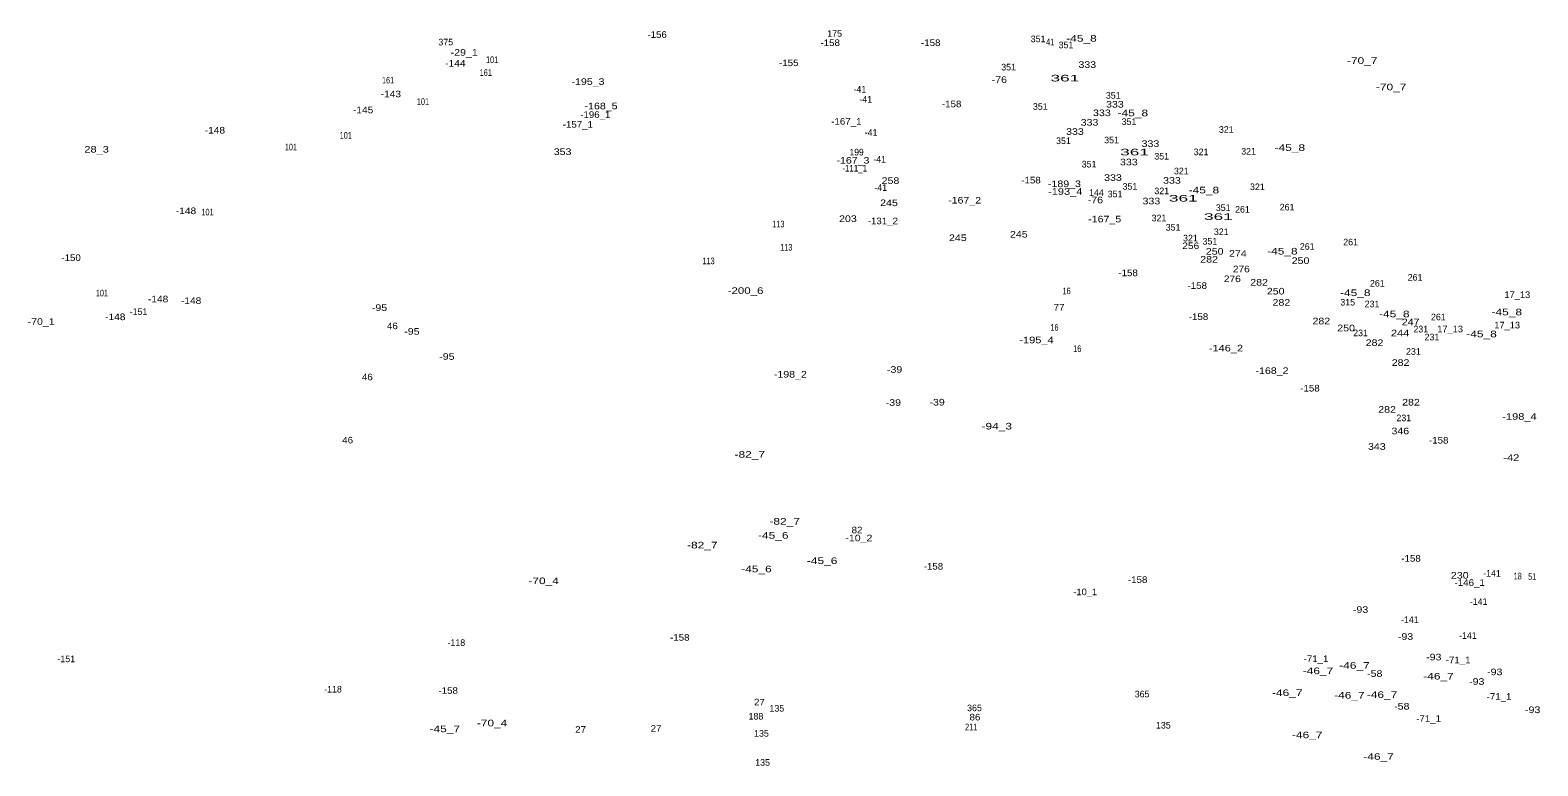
# Model space of a CAD drawing. Extents: x -662996 to -659766, y -998554 to -993949.
# Drawn here: x -661500 to -660587, y -997860 to -997415 of the extents above; entities that cross this region are included whole.
import ezdxf
from ezdxf.enums import TextEntityAlignment as Align

# ---------------------------------------------------------------- set-up
doc = ezdxf.new("R2010")
doc.units = 0
doc.header["$LTSCALE"] = 1.6
doc.layers.add('24', color=7, linetype='Continuous')

msp = doc.modelspace()

# ---------------------------------------------------------------- texts
at = {"layer": '24'}
for s, width, p in [('-156', 1.1, (-661120.29, -997419.77)), ('-29_1', 1.2, (-661237.091, -997430.59)), ('-158', 1.1, (-661015.5, -997424.74)), ('-158', 1.1, (-660954.64, -997424.74)), ('41', 0.85, (-660882.27, -997424.26)), ('-45_8', 1.35, (-660863.36, -997422.11)), ('-144', 1.15, (-661242.45, -997437.19)), ('101', 0.8, (-661220.2, -997434.99)), ('-155', 1.1, (-661040.581, -997436.9)), ('333', 1.2, (-660859.84, -997437.96)), ('-70_7', 1.35, (-660693.39, -997435.52)), ('161', 0.8, (-661283.181, -997447.39)), ('161', 0.8, (-661224.041, -997442.78)), ('-195_3', 1.2, (-661162.15, -997448.25)), ('-76', 1.2, (-660913.11, -997447.1)), ('361', 1.95, (-660873.423, -997446.17)), ('-143', 1.15, (-661281.52, -997455.72)), ('-70_7', 1.35, (-660675.87, -997451.52)), ('-145', 1.15, (-661298.31, -997465.43)), ('101', 0.8, (-661262.06, -997460.35)), ('-168_5', 1.2, (-661154.24, -997463.01)), ('-158', 1.1, (-660941.971, -997461.81)), ('333', 1.2, (-660851, -997467.15)), ('333', 1.2, (-660843.13, -997461.97)), ('-45_8', 1.35, (-660832.25, -997467.25)), ('-157_1', 1.1, (-661168.301, -997474.16)), ('-196_1', 1.1, (-661157.71, -997468.22)), ('-167_1', 1.1, (-661005.71, -997472.34)), ('333', 1.2, (-660858.49, -997472.92)), ('-148', 1.15, (-661388.05, -997477.68)), ('101', 0.8, (-661308.81, -997480.77)), ('333', 1.2, (-660867.319, -997478.48)), ('333', 1.2, (-660821.62, -997485.79)), ('28_3', 1.25, (-661459.66, -997489.21)), ('101', 0.8, (-661342.03, -997487.88)), ('353', 1.2, (-661177.53, -997490.67)), ('199', 0.95, (-660999.49, -997490.95)), ('361', 1.95, (-660831.233, -997490.92)), ('-45_8', 1.35, (-660737.21, -997488.19)), ('-167_3', 1.2, (-661001.73, -997495.92)), ('-111_1', 0.9, (-661000.67, -997500.68)), ('333', 1.2, (-660834.679, -997496.93)), ('258', 1.2, (-660979.01, -997508.19)), ('-158', 1.1, (-660893.921, -997507.89)), ('-189_3', 1.2, (-660873.671, -997510.12)), ('333', 1.2, (-660844.29, -997506.34)), ('333', 1.2, (-660808.579, -997508.06)), ('245', 1.2, (-660979.91, -997521.62)), ('-167_2', 1.2, (-660934.11, -997520.06)), ('-193_4', 1.25, (-660873.19, -997514.75)), ('-76', 1.2, (-660854.939, -997519.9)), ('333', 1.2, (-660821.049, -997520.55)), ('361', 1.95, (-660801.723, -997518.85)), ('-45_8', 1.35, (-660789.24, -997513.93)), ('-148', 1.15, (-661405.53, -997526.47)), ('101', 0.8, (-661392.53, -997527.25)), ('203', 1.2, (-661004.77, -997531.22)), ('-167_5', 1.2, (-660849.3, -997531.47)), ('361', 1.95, (-660780.473, -997529.96)), ('113', 0.8, (-661046.9, -997534.49)), ('-131_2', 1.1, (-660983.61, -997532.57)), ('245', 1.2, (-660901.29, -997540.67)), ('113', 0.8, (-661042.1, -997548.51)), ('245', 1.2, (-660938.209, -997542.77)), ('256', 1.15, (-660797.19, -997547.62)), ('-150', 1.1, (-661475.12, -997554.83)), ('113', 0.8, (-661089.14, -997556.77)), ('282', 1.2, (-660786.1, -997555.81)), ('250', 1.2, (-660782.709, -997551.01)), ('274', 1.2, (-660768.67, -997552.29)), ('-45_8', 1.35, (-660741.74, -997550.9)), ('250', 1.2, (-660730.73, -997556.63)), ('-158', 1.1, (-660835.13, -997564.01)), ('276', 1.15, (-660772.03, -997567.62)), ('276', 1.15, (-660766.6, -997561.71)), ('101', 0.8, (-661456.46, -997576.23)), ('-200_6', 1.3, (-661066.75, -997574.76)), ('16', 0.8, (-660872.341, -997574.94)), ('-158', 1.1, (-660793.27, -997571.69)), ('282', 1.2, (-660755.829, -997569.71)), ('250', 1.2, (-660745.77, -997575.1)), ('-45_8', 1.35, (-660697.58, -997576.06)), ('17_13', 1.05, (-660599.48, -997577.2)), ('-148', 1.15, (-661422.42, -997579.86)), ('-148', 1.15, (-661402.45, -997580.82)), ('-95', 1.2, (-661288.39, -997585.07)), ('77', 1.1, (-660876.931, -997584.83)), ('282', 1.2, (-660742.309, -997581.9)), ('-70_1', 1.2, (-661493.231, -997593.46)), ('-148', 1.15, (-661448.34, -997590.62)), ('-158', 1.1, (-660792.51, -997590.52)), ('282', 1.2, (-660718.13, -997593.14)), ('-45_8', 1.35, (-660673.96, -997588.9)), ('247', 1.2, (-660664.06, -997593.71)), ('-45_8', 1.35, (-660605.84, -997587.71)), ('46', 1.1, (-661280.59, -997596.1)), ('-95', 1.2, (-661268.77, -997599.45)), ('-195_4', 1.25, (-660890.58, -997604.61)), ('16', 0.8, (-660879.731, -997597.03)), ('250', 1.2, (-660703.14, -997597.39)), ('244', 1.25, (-660670.44, -997600.43)), ('17_13', 1.05, (-660640.18, -997597.94)), ('-45_8', 1.35, (-660621.15, -997601)), ('17_13', 1.05, (-660605.62, -997595.64)), ('16', 0.8, (-660865.9, -997609.9)), ('-146_2', 1.25, (-660775.89, -997609.57)), ('282', 1.2, (-660685.949, -997606.29)), ('-95', 1.2, (-661247.58, -997614.62)), ('-39', 1.2, (-660976.5, -997622.49)), ('282', 1.2, (-660670.15, -997618.29)), ('46', 1.1, (-661295.76, -997627.03)), ('-198_2', 1.2, (-661039.64, -997625.38)), ('-168_2', 1.2, (-660748.01, -997623.22)), ('-158', 1.1, (-660725.03, -997633.81)), ('-39', 1.2, (-660977.26, -997642.47)), ('-39', 1.2, (-660950.77, -997642.28)), ('282', 1.2, (-660678.329, -997646.67)), ('282', 1.2, (-660663.86, -997642.29)), ('-94_3', 1.35, (-660914.67, -997656.79)), ('-198_4', 1.25, (-660598.17, -997650.94)), ('46', 1.1, (-661307.66, -997665.25)), ('346', 1.2, (-660670.33, -997659.69)), ('-158', 1.1, (-660647.081, -997665.31)), ('-82_7', 1.35, (-661064.19, -997673.86)), ('343', 1.2, (-660684.54, -997669.09)), ('-42', 1.25, (-660603.11, -997675.84)), ('-45_6', 1.35, (-661049.96, -997722.88)), ('-82_7', 1.35, (-661043.06, -997714.39)), ('82', 1.1, (-660999.27, -997719.64)), ('-82_7', 1.35, (-661092.95, -997728.78)), ('-10_2', 1.2, (-660998.14, -997724.44)), ('-45_6', 1.35, (-661020.39, -997738.24)), ('-158', 1.1, (-660663.821, -997736.81)), ('-70_4', 1.35, (-661189.01, -997750.38)), ('-45_6', 1.35, (-661060.14, -997743.24)), ('-158', 1.1, (-660952.981, -997741.62)), ('-158', 1.1, (-660829.351, -997749.67)), ('230', 1.2, (-660634.319, -997747.05)), ('18', 0.8, (-660599.23, -997747.52)), ('51', 0.8, (-660590.5, -997747.77)), ('-10_1', 1.05, (-660861.1, -997757.09)), ('-146_1', 1.1, (-660628.31, -997751.44)), ('-93', 1.2, (-660694.37, -997767.78)), ('-158', 1.1, (-661106.571, -997784.63)), ('-93', 1.2, (-660667.16, -997784.11)), ('-46_7', 1.35, (-660720.16, -997804.86)), ('-71_1', 1.1, (-660721.361, -997797.51)), ('-46_7', 1.35, (-660698.081, -997801.59)), ('-93', 1.2, (-660650.06, -997796.55)), ('-71_1', 1.1, (-660635.301, -997798.27)), ('-93', 1.2, (-660613.14, -997805.5)), ('-58', 1.2, (-660685.8, -997806.5)), ('-46_7', 1.35, (-660647.201, -997808.12)), ('-93', 1.2, (-660624.02, -997811.33)), ('-158', 1.1, (-661246.801, -997816.77)), ('-46_7', 1.35, (-660738.78, -997818.11)), ('-46_7', 1.35, (-660701.15, -997819.65)), ('-46_7', 1.35, (-660681.37, -997819.26)), ('-71_1', 1.1, (-660610.551, -997820.37)), ('27', 1.1, (-661058.34, -997823.81)), ('86', 1.1, (-660927.87, -997832.88)), ('-58', 1.2, (-660669.42, -997826.31)), ('-93', 1.2, (-660590.2, -997828.44)), ('-45_7', 1.35, (-661248.85, -997840)), ('-70_4', 1.35, (-661220.23, -997836.46)), ('27', 1.1, (-661166.63, -997840.33)), ('27', 1.1, (-661120.94, -997839.75)), ('211', 0.8, (-660930.14, -997838.81)), ('-71_1', 1.1, (-660653.201, -997833.7)), ('-46_7', 1.35, (-660726.691, -997843.66)), ('-46_7', 1.35, (-660683.49, -997856.72))]:
    msp.add_text(s, height=4, dxfattribs=dict(at, width=width)).set_placement(p, align=Align.CENTER)
for s, p in [('175', (-661012.811, -997419.13)), ('375', (-661248.273, -997424.36)), ('351', (-660889.65, -997422.41)), ('351', (-660872.75, -997426.06)), ('351', (-660907.5, -997439.5)), ('-41', (-660997.55, -997452.92)), ('351', (-660844.14, -997456.6)), ('-41', (-660993.99, -997458.97)), ('351', (-660888.299, -997463.32)), ('351', (-660834.579, -997472.49)), ('-41', (-660990.73, -997479.02)), ('351', (-660874.29, -997484.07)), ('351', (-660845.14, -997483.63)), ('321', (-660775.699, -997477.26)), ('351', (-660814.799, -997493.43)), ('321', (-660790.929, -997490.79)), ('321', (-660762.179, -997490.41)), ('-41', (-660985.54, -997495.26)), ('351', (-660858.77, -997498.23)), ('321', (-660802.929, -997502.41)), ('-41', (-660984.91, -997512.39)), ('351', (-660834, -997511.67)), ('321', (-660756.85, -997511.93)), ('144', (-660854.31, -997515.44)), ('351', (-660843.03, -997516.28)), ('321', (-660814.76, -997514.39)), ('321', (-660816.449, -997530.79)), ('351', (-660777.549, -997524.54)), ('261', (-660765.91, -997525.57)), ('261', (-660738.87, -997524.24)), ('351', (-660807.89, -997536.45)), ('321', (-660778.74, -997539.15)), ('321', (-660797.41, -997542.98)), ('351', (-660785.62, -997544.9)), ('261', (-660726.701, -997548.04)), ('261', (-660700.41, -997545.37)), ('261', (-660661.38, -997566.71)), ('261', (-660684.24, -997570.33)), ('315', (-660702.179, -997581.76)), ('231', (-660687.439, -997582.82)), ('-151', (-661434.27, -997587.5)), ('261', (-660647.291, -997590.71)), ('231', (-660694.39, -997600.34)), ('231', (-660657.929, -997598.06)), ('231', (-660651.16, -997602.86)), ('231', (-660662.4, -997611.58)), ('231', (-660668.209, -997651.77)), ('-141', (-660614.81, -997745.86)), ('-141', (-660622.87, -997762.95)), ('-141', (-660664.54, -997773.9)), ('-141', (-660629.4, -997783.5)), ('-118', (-661241.88, -997787.79)), ('-151', (-661478.051, -997797.63)), ('-118', (-661316.52, -997815.98)), ('365', (-660826.663, -997818.92)), ('188', (-661060.449, -997832.34)), ('135', (-661047.809, -997827.55)), ('365', (-660928.153, -997827.3)), ('135', (-660813.79, -997837.78)), ('135', (-661057.12, -997842.72)), ('135', (-661056.449, -997860.3))]:
    msp.add_text(s, height=4, dxfattribs=at).set_placement(p, align=Align.CENTER)

doc.saveas('drawing.dxf')
